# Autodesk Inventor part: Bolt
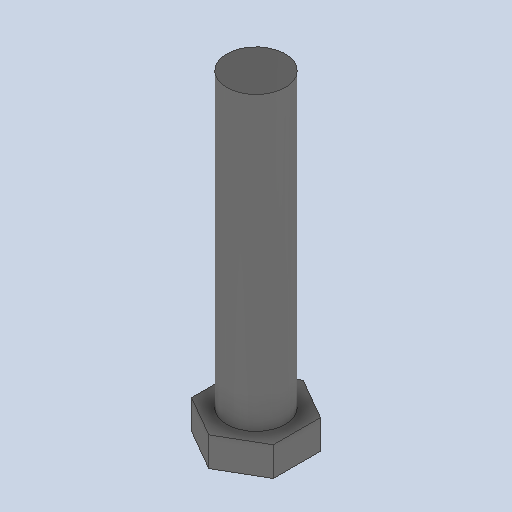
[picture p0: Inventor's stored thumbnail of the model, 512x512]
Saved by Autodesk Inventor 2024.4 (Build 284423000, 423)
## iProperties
Created: 2025-07
Part Number: Bolt
Material: Generic
Document SubType Name: Modeling
Designer: AdminForWorker
Density: 1 g/cm^3
Appearance: Default
Title: Bolt v1
Author: AdminForWorker
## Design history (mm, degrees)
feature "Body1"
body "Solid1"
